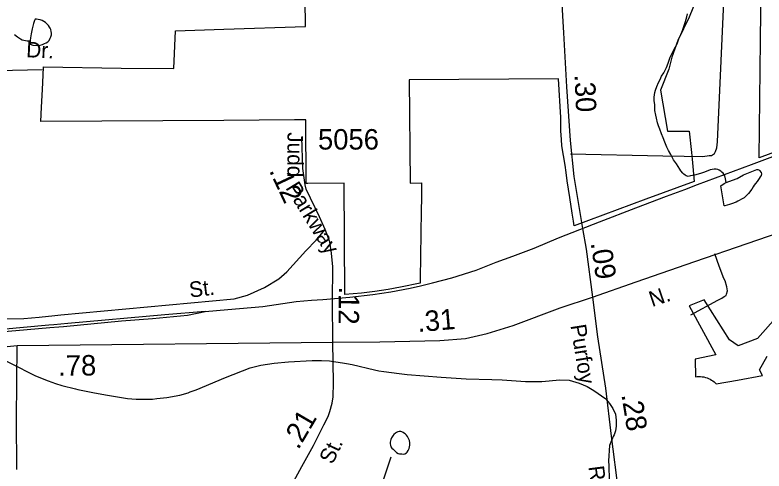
# Model space of a CAD drawing. Extents: x 2001466 to 2224147, y 644118 to 847247.
# Drawn here: x 2063724 to 2068297, y 669606 to 672391 of the extents above; entities that cross this region are included whole.
import ezdxf

# ---------------------------------------------------------------- set-up
doc = ezdxf.new("R2010")
doc.units = 0
for name, color, linetype in [('Exist Boundary Political City Limit New', 7, 'Continuous'), ('Exist Hydrographic Creek Single Shore', 7, 'Continuous'), ('Exist Hydrographic Misc Water Feature', 7, 'Continuous'), ('Exist Railroad Mainline', 7, 'Continuous'), ('Exist Railroad Siding', 7, 'Continuous'), ('Exist Road Non-System Type 51', 7, 'Continuous'), ('Exist Road Non-System Type 51 Label', 7, 'Continuous'), ('Exist Road Primary US Attributed', 7, 'Continuous'), ('Exist Road Primary US Label', 7, 'Continuous'), ('Exist Road Primary US Mileage Hundredths English Label', 7, 'Continuous'), ('Exist Road Secondary Mileage Hundredths English Label', 7, 'Continuous'), ('Exist Road Secondary Type 51 Attributed', 7, 'Continuous'), ('Exist Road Secondary Type 51 Label', 7, 'Continuous'), ('Exist Road Secondary Type 51 Number Label', 7, 'Continuous'), ('Map Preparation Boundary City Limit Buffer Line', 7, 'Continuous')]:
    doc.layers.add(name, color=color, linetype=linetype)

msp = doc.modelspace()

# ---------------------------------------------------------------- linework, layer by layer
at = {"layer": 'Exist Boundary Political City Limit New'}
for points in [[(2065738, 670683.3), (2065734, 671363.3), (2065512.2, 671362.5), (2065501.5, 671362.4), (2065500.1, 671750.2), (2065430, 671749.7), (2065000, 671747.1), (2063882.2, 671740.3), (2063886.4, 671827.8), (2063891.6, 671936.2), (2063895.8, 672023.8), (2063897.6, 672073.8), (2064372.4, 672067), (2064693.1, 672064.7), (2064703.1, 672294), (2065000, 672303.5), (2065496.6, 672319.8), (2065489.2, 672981.5)], [(2068496.8, 671603.3), (2068267.1, 671519.3), (2068275.2, 672234.5), (2068284, 672935.8)], [(2067883.5, 672490.1), (2067839, 672378.1), (2067770.8, 672235.2), (2067733.8, 672132.6), (2067716.2, 672059.8), (2067665.4, 671931.4), (2067706.6, 671682.1), (2067840.1, 671681), (2067853.2, 671552.2), (2067857.1, 671510.6), (2067870.1, 671373.8), (2067575.9, 671265.8), (2067136.6, 671103.7), (2067132.6, 671132.4), (2067125.5, 671180.9), (2067110.6, 671275.8), (2067095.5, 671378.6), (2067088.5, 671429.1), (2067082.8, 671473.8), (2067062.6, 671592.8), (2067059.8, 671629.7), (2067055.6, 671684.5), (2067056.4, 671764.5), (2067042.6, 672000.1), (2066130.4, 671994.4), (2066136.9, 671364.8), (2066206, 671365), (2066204.8, 671266.1), (2066204, 671202.1), (2066203.9, 671195.1), (2066198.4, 670779.1), (2066198.1, 670753.1), (2066077.8, 670728.9), (2066001.5, 670715.1), (2065920.4, 670702.7), (2065839, 670692.6), (2065738, 670683.3)], [(2068384.8, 670560.4), (2068257.6, 670415.1), (2068139.5, 670369.8), (2068085, 670406.1), (2067930.6, 670651.1), (2067839.9, 670614.8), (2068003.2, 670315.2), (2067876.1, 670288), (2067878.9, 670181.9), (2067889, 670182.9), (2067899, 670183.3), (2067909.1, 670183), (2067919.2, 670182), (2067929.1, 670180.2), (2067939, 670177.8), (2067948.6, 670174.8), (2067958, 670171), (2067967.1, 670166.6), (2067975.9, 670161.6), (2067984.2, 670155.9), (2067992.2, 670149.8), (2067999.8, 670143.1), (2068005.4, 670137.8), (2068135, 670161), (2068286.9, 670189.7), (2068268.8, 670224.1), (2068316.5, 670307.3)]]:
    msp.add_lwpolyline(points, dxfattribs=at)
at = {"layer": 'Exist Hydrographic Creek Single Shore'}
msp.add_lwpolyline([(2066179.8, 668236.4), (2066132.3, 668352.2), (2066106.2, 668608.7), (2066031.2, 668843.1), (2065972.3, 668942.7), (2065930.3, 669117.5), (2065938.3, 669448.7), (2066021.3, 669693)], dxfattribs=at)
at = {"layer": 'Exist Hydrographic Misc Water Feature'}
for p, q in [((2063824.8, 670200.3), (2063850.4, 670187.5)), ((2064093.4, 670107.1), (2064108.4, 670103.3)), ((2067258.2, 670096.8), (2067330.4, 670045.7)), ((2067258.2, 670096.8), (2067330.4, 670045.7)), ((2067330.4, 670045.7), (2067343.7, 670030)), ((2067330.4, 670045.7), (2067343.7, 670030)), ((2067393.7, 669916.4), (2067394.4, 669911.5))]:
    msp.add_line(p, q, dxfattribs=at)
for points in [[(2068065.9, 671367.2), (2068061.8, 671391), (2068057.5, 671409), (2068047.5, 671425.2), (2068039.5, 671431.2), (2068033.7, 671437), (2068023.7, 671442.9), (2068013.6, 671446.9), (2068003.8, 671448.8), (2067991.5, 671449), (2067967.9, 671444.9), (2067943.7, 671434.8), (2067927.7, 671428.7), (2067915.6, 671424.8), (2067895.5, 671419), (2067871.5, 671412.9), (2067859.8, 671410.6), (2067847.9, 671408.8), (2067833.8, 671404.9), (2067821.5, 671408.7), (2067816, 671412.8), (2067808, 671418.5), (2067801.8, 671424.7), (2067789.5, 671438.7), (2067781.7, 671450.4), (2067771.7, 671466.5), (2067761.6, 671482.7), (2067743.6, 671506.5), (2067727.6, 671538.6), (2067713.4, 671562.6), (2067703.4, 671584.4), (2067691.3, 671614.2), (2067681.2, 671640.5), (2067671.2, 671664.3), (2067661.3, 671694.2), (2067653.1, 671714.5), (2067647.2, 671732.4), (2067639.2, 671760.4), (2067635.3, 671780), (2067629.4, 671808.1), (2067629.1, 671842.3), (2067626.9, 671868.1), (2067626.9, 671890.1), (2067630.6, 671918.3), (2067634.7, 671932.3), (2067643.1, 671954.1), (2067652.5, 671978.2), (2067662.8, 671996.1), (2067670.8, 672016.4), (2067684.7, 672038.3), (2067700.7, 672070.3), (2067710.6, 672096.4), (2067724.5, 672134.4), (2067734.5, 672154.4), (2067748.3, 672182.4), (2067766.3, 672214.5), (2067776, 672244.6), (2067788.3, 672272.4), (2067798.3, 672296.4), (2067808.4, 672326.5), (2067816.2, 672350.5), (2067826, 672380.6), (2067829.7, 672398.3)], [(2063817.4, 672231), (2063817.4, 672222.9), (2063817.4, 672213.2), (2063833.4, 672207.1), (2063863.2, 672205), (2063877.3, 672207.3), (2063893.1, 672211), (2063905.2, 672217.3), (2063915.2, 672221.1), (2063925.1, 672227.3), (2063932.9, 672235.4), (2063939, 672249.5), (2063942.9, 672257.4), (2063947, 672269.4), (2063947, 672279.1), (2063944.8, 672291.2), (2063942.9, 672303.2), (2063939.2, 672311.1), (2063935.1, 672317.4), (2063929.2, 672327.2), (2063921.2, 672335.3), (2063910.9, 672345.4), (2063900.9, 672351.4), (2063890.6, 672357), (2063876.9, 672361.1), (2063866.6, 672363.1), (2063855.2, 672365.2), (2063847, 672365.2), (2063842.7, 672357), (2063840.8, 672351.2), (2063836.7, 672339.2), (2063833.2, 672323.1), (2063828.9, 672307.1), (2063825, 672287), (2063823.2, 672275.2), (2063821.1, 672262.9), (2063819.1, 672251.1), (2063817.2, 672235.1), (2063817.4, 672231)], [(2063817.4, 672231), (2063799.2, 672231), (2063778.9, 672234.8), (2063769, 672237.1), (2063757.4, 672243), (2063738.9, 672255.1), (2063721.3, 672270.7)], [(2068065.9, 671367.2), (2068081.7, 671373.3), (2068131.9, 671393.3), (2068171.7, 671415.3), (2068211.3, 671431.6), (2068241.8, 671443.6), (2068253.5, 671447.5), (2068259.5, 671447.4), (2068265.6, 671445.7), (2068269.5, 671441.4), (2068279.4, 671429.4), (2068281.6, 671421.7), (2068279.8, 671411.4), (2068273.8, 671403.4), (2068267.5, 671393.4), (2068261.9, 671385.4), (2068253.9, 671373.6), (2068243.9, 671361.3), (2068235.9, 671351.6), (2068230, 671341.5), (2068221.5, 671327.4), (2068202.1, 671301.6), (2068184.2, 671281.5), (2068176, 671273.5), (2068159.8, 671265.4), (2068145.7, 671257.4), (2068136, 671253.1), (2068125.8, 671247.4), (2068097.7, 671237.1), (2068086, 671233.1), (2068072.3, 671229.2), (2068057.9, 671225.2), (2068054, 671225), (2068045.8, 671275.3), (2068039.9, 671311.1), (2068031.9, 671347.2), (2068053.8, 671360.9), (2068065.9, 671367.2)], [(2063443.2, 670371.3), (2063512.3, 670348), (2063571.4, 670325.3), (2063615.3, 670305.2), (2063824.8, 670200.3)], [(2063443.2, 670371.3), (2063512.3, 670348), (2063571.4, 670325.3), (2063615.3, 670305.2), (2063824.8, 670200.3)], [(2064793.9, 670088.6), (2064830.4, 670102), (2065009.4, 670176.2), (2065160.3, 670235.3), (2065224.3, 670252.3), (2065305.3, 670264.8), (2065394.3, 670273.5), (2065538.2, 670281.8), (2065595.2, 670281.7), (2065643.2, 670278.2)], [(2064793.9, 670088.6), (2064830.4, 670102), (2065009.4, 670176.2), (2065160.3, 670235.3), (2065224.3, 670252.3), (2065305.3, 670264.8), (2065394.3, 670273.5), (2065538.2, 670281.8), (2065595.2, 670281.7), (2065643.2, 670278.2)], [(2065643.2, 670278.2), (2065655.3, 670277.3), (2065723.4, 670267.4), (2065748.2, 670262.4)], [(2065643.2, 670278.2), (2065655.3, 670277.3), (2065723.4, 670267.4), (2065748.2, 670262.4)], [(2065748.2, 670262.4), (2065782.2, 670255.8), (2065919.2, 670223.3), (2065946.1, 670218.3)], [(2065748.2, 670262.4), (2065782.2, 670255.8), (2065919.2, 670223.3), (2065946.1, 670218.3)], [(2063850.4, 670187.5), (2063926.3, 670155.7), (2063972, 670140.8)], [(2063850.4, 670187.5), (2063926.3, 670155.7), (2063972, 670140.8)], [(2065946.1, 670218.3), (2065975.6, 670212.9), (2066069.9, 670201.6)], [(2065946.1, 670218.3), (2065975.6, 670212.9), (2066069.9, 670201.6)], [(2066069.9, 670201.6), (2066117.3, 670195.9), (2066325.2, 670178.2)], [(2066069.9, 670201.6), (2066117.3, 670195.9), (2066325.2, 670178.2)], [(2066325.2, 670178.2), (2066479.2, 670169.3), (2066634, 670164.7)], [(2066325.2, 670178.2), (2066479.2, 670169.3), (2066634, 670164.7)], [(2063972, 670140.8), (2064009.4, 670128.5), (2064093.4, 670107.1)], [(2063972, 670140.8), (2064009.4, 670128.5), (2064093.4, 670107.1)], [(2066634, 670164.7), (2066697.4, 670162.8), (2066840.3, 670153.3), (2066889.3, 670152), (2066939.6, 670153.2), (2067050.3, 670162.8)], [(2066634, 670164.7), (2066697.4, 670162.8), (2066840.3, 670153.3), (2066889.3, 670152), (2066939.6, 670153.2), (2067050.3, 670162.8)], [(2067050.3, 670162.8), (2067106.3, 670160), (2067167.4, 670143.4)], [(2067050.3, 670162.8), (2067106.3, 670160), (2067167.4, 670143.4)], [(2067167.4, 670143.4), (2067216.4, 670121.1), (2067258.2, 670096.8)], [(2067167.4, 670143.4), (2067216.4, 670121.1), (2067258.2, 670096.8)], [(2064108.4, 670103.3), (2064198.4, 670084.8), (2064277.2, 670070.5), (2064410, 670049.5), (2064463.8, 670045.4)], [(2064108.4, 670103.3), (2064198.4, 670084.8), (2064277.2, 670070.5), (2064410, 670049.5), (2064463.8, 670045.4)], [(2064730.5, 670069.5), (2064781.4, 670084.1), (2064793.9, 670088.6)], [(2064730.5, 670069.5), (2064781.4, 670084.1), (2064793.9, 670088.6)], [(2064463.8, 670045.4), (2064481.4, 670044), (2064564.2, 670045.6), (2064589.5, 670048.2)], [(2064463.8, 670045.4), (2064481.4, 670044), (2064564.2, 670045.6), (2064589.5, 670048.2)], [(2064589.5, 670048.2), (2064650.4, 670054.3), (2064730.5, 670069.5)], [(2064589.5, 670048.2), (2064650.4, 670054.3), (2064730.5, 670069.5)], [(2067343.7, 670030), (2067354.2, 670017.8), (2067374.3, 669987.6)], [(2067343.7, 670030), (2067354.2, 670017.8), (2067374.3, 669987.6)], [(2067374.3, 669987.6), (2067389.2, 669953.1), (2067393.7, 669916.4)], [(2067374.3, 669987.6), (2067389.2, 669953.1), (2067393.7, 669916.4)], [(2067394.4, 669911.5), (2067393.3, 669880.2), (2067389.2, 669850.6), (2067382.5, 669826.9), (2067375.7, 669816.2)], [(2067394.4, 669911.5), (2067393.3, 669880.2), (2067389.2, 669850.6), (2067382.5, 669826.9), (2067375.7, 669816.2)], [(2066033.2, 669739.7), (2066053.1, 669719.7), (2066063.2, 669713.8), (2066071.2, 669711.8), (2066085.1, 669709.8), (2066093.1, 669707.8), (2066103.2, 669711.8), (2066113.2, 669717.8), (2066119.1, 669721.8), (2066125.1, 669731.9), (2066131.2, 669743.9), (2066133.1, 669753.9), (2066135.1, 669763.9), (2066135.1, 669777.9), (2066133.1, 669791.9), (2066125.1, 669807.9), (2066121, 669815.9), (2066115, 669823.9), (2066108.9, 669829.9), (2066102.9, 669835.8), (2066092.9, 669841.8), (2066084.9, 669845.8), (2066079, 669847.8), (2066068.9, 669847.8), (2066060.9, 669845.7), (2066052.9, 669841.7), (2066047, 669837.7), (2066037.1, 669829.7), (2066031, 669821.6), (2066027.1, 669813.7), (2066023, 669807.7), (2066019.1, 669797.7), (2066017, 669789.7), (2066015, 669781.7), (2066015, 669771.7), (2066017.2, 669763.7), (2066019.1, 669753.7), (2066025.2, 669745.7), (2066033.2, 669739.7)], [(2067375.7, 669816.2), (2067353.4, 669760.8), (2067347.2, 669667.1), (2067348.2, 669638.2)], [(2067375.7, 669816.2), (2067353.4, 669760.8), (2067347.2, 669667.1), (2067348.2, 669638.2)], [(2067348.2, 669638.2), (2067351.3, 669552.9), (2067360.3, 669439.8)], [(2067348.2, 669638.2), (2067351.3, 669552.9), (2067360.3, 669439.8)]]:
    msp.add_lwpolyline(points, dxfattribs=at)
at = {"layer": 'Exist Railroad Mainline'}
for points in [[(2067171.7, 671081), (2067291.9, 671127.3), (2067513.8, 671213.4), (2067701.8, 671283.5), (2067812.6, 671326.1), (2067889.7, 671355.7), (2068220.9, 671477.9), (2068253.6, 671489.9), (2068637.6, 671634.1), (2069017.5, 671776.4), (2069389.4, 671910.9), (2069773.3, 672053.1), (2070137.2, 672185.3), (2070333.9, 672257.2)], [(2064886.1, 670579.1), (2065024.4, 670592.8), (2065236.4, 670610.7), (2065440.2, 670641.9), (2065534.9, 670648.4), (2065603, 670653.9), (2065769.1, 670668.1), (2065908.3, 670684.5), (2066018.4, 670700.7), (2066135.7, 670721.6), (2066200.4, 670736.2), (2066273.6, 670755.7), (2066391.1, 670785.6), (2066538.6, 670832), (2066660.6, 670880.7), (2066763.1, 670917.3), (2066892.5, 670966.1), (2067041.9, 671030.9), (2067171.7, 671081)], [(2061615.3, 670546.4), (2061794.5, 670479.1), (2061925.3, 670432), (2062043.1, 670401), (2062164.4, 670375.6), (2062260.2, 670360.4), (2062367.4, 670352.5), (2062477.3, 670350.2), (2062619, 670358.9), (2062757, 670369.6), (2062933.2, 670385.8), (2063244.5, 670414), (2063542.8, 670447.3), (2063935.9, 670482.5)], [(2063935.9, 670482.5), (2063992.1, 670487.1), (2064019.8, 670489.3), (2064375.1, 670522.3), (2064564.3, 670536.5), (2064777.1, 670557), (2064886.1, 670579.1)]]:
    msp.add_lwpolyline(points, dxfattribs=at)
at = {"layer": 'Exist Railroad Siding'}
for points in [[(2063930.4, 670495.7), (2063643.2, 670470.4), (2063452.6, 670445.2), (2062937.2, 670419.6), (2062850.9, 670412.8), (2062568.7, 670389.7), (2062401.2, 670389.1), (2062241.6, 670404.4), (2062146.3, 670419.1), (2062022.8, 670447.3), (2061889.2, 670481.7), (2061708.9, 670535.5), (2061615.3, 670546.4)], [(2064886.1, 670579.1), (2064638.3, 670560.4), (2064046.2, 670506.3), (2063960.6, 670498.2), (2063930.4, 670495.7)]]:
    msp.add_lwpolyline(points, dxfattribs=at)
at = {"layer": 'Exist Road Non-System Type 51'}
for p, q in [((2063524, 672049.3), (2063890.6, 672058.6)), ((2067115.7, 671543.8), (2067678, 671530.8)), ((2068023.3, 670857.6), (2067995.3, 670932))]:
    msp.add_line(p, q, dxfattribs=at)
for points in [[(2067678, 671530.8), (2067809.4, 671527.8), (2067923.4, 671527.4), (2067961.5, 671532.7), (2067975.5, 671532.4), (2067993.8, 671546), (2068000, 671557.9), (2068008.5, 671579.7), (2068013.2, 671615.6), (2068057.4, 672608.7), (2067994.8, 672697.6), (2067991.2, 672698.1), (2067939.2, 672697.1), (2067845.6, 672699.7)], [(2067849.1, 670559.1), (2068015.5, 670649.6), (2068039.8, 670661.1), (2068054, 670670.8), (2068066.1, 670678.5), (2068068.3, 670686.5), (2068072.7, 670706.4), (2068069.2, 670730.5), (2068059.9, 670766.7), (2068052.2, 670780.8), (2068023.3, 670857.6)], [(2063736.1, 670371.8), (2063731.9, 669924.3), (2063732.5, 669614.2)]]:
    msp.add_lwpolyline(points, dxfattribs=at)
at = {"layer": 'Exist Road Primary US Attributed'}
for points in [[(2067248.5, 670668.2), (2067515.3, 670761.4), (2067873.8, 670885), (2068512.2, 671104.9), (2069417.4, 671419.1), (2069697.9, 671513.4), (2069984.6, 671607.6), (2070426.2, 671762.6)], [(2065664.7, 670392.6), (2065950.3, 670394.3), (2066318.1, 670402.8), (2066474.1, 670415.8), (2066605.9, 670445.2), (2066765, 670495.4), (2067051.7, 670602.3), (2067248.5, 670668.2)], [(2061546.2, 670250.4), (2061679.9, 670254.6), (2061992.8, 670260.9), (2062298.4, 670265), (2062649.5, 670278.7), (2063102.2, 670317.4), (2063470.5, 670346.7), (2063738.4, 670371.9), (2065664.7, 670392.6)]]:
    msp.add_lwpolyline(points, dxfattribs=at)
at = {"layer": 'Exist Road Secondary Type 51 Attributed'}
for points in [[(2067047.9, 672703.9), (2067073.2, 672281.5), (2067090.5, 671953.1), (2067112.6, 671623.8), (2067136.3, 671404.3), (2067189.3, 671087.7)], [(2065617, 671080), (2065583.9, 671158.4), (2065501.1, 671327.9), (2065495.4, 671352.8), (2065480.7, 671452.5), (2065475, 671645.3)], [(2061545, 670645.5), (2061608, 670629.6), (2061734.2, 670612.3), (2063279.4, 670542.3), (2063591.9, 670534.7), (2063778.8, 670538.2), (2063872.5, 670545.9), (2063967.9, 670555.3), (2064004.5, 670559.5), (2065061.2, 670658.2), (2065142.6, 670680.5), (2065247.6, 670726.5), (2065334.3, 670779), (2065384.6, 670821.9), (2065500.4, 670949.7), (2065562, 671015.6), (2065617, 671080)], [(2065664.7, 670392.6), (2065662.6, 670641.3), (2065665.1, 670852.6), (2065656.2, 670936.9), (2065646.8, 671005.1), (2065617, 671080)], [(2067189.3, 671087.7), (2067210.4, 670961.4), (2067248.5, 670668.2)], [(2067248.5, 670668.2), (2067280.8, 670424.7), (2067328.3, 670111), (2067363.7, 669818.4), (2067405.9, 669484.7), (2067446.5, 669206.9)], [(2065320.2, 669350.5), (2065475.1, 669633), (2065546.4, 669760.7), (2065610.2, 669888.3), (2065635.7, 669939.4), (2065646, 669969.2), (2065659.6, 670019.5), (2065665.5, 670058.7), (2065668.1, 670143.8), (2065664.7, 670392.6)]]:
    msp.add_lwpolyline(points, dxfattribs=at)
at = {"layer": 'Map Preparation Boundary City Limit Buffer Line'}
for points in [[(2065738, 670683.3), (2065734, 671363.3), (2065512.2, 671362.5), (2065501.5, 671362.4), (2065500.1, 671750.2), (2065430, 671749.7), (2065000, 671747.1), (2063882.2, 671740.3), (2063886.4, 671827.8), (2063891.6, 671936.2), (2063895.8, 672023.8), (2063897.6, 672073.8), (2064372.4, 672067), (2064693.1, 672064.7), (2064703.1, 672294), (2065000, 672303.5), (2065496.6, 672319.8), (2065489.2, 672981.5)], [(2068496.8, 671603.3), (2068267.1, 671519.3), (2068275.2, 672234.5), (2068284, 672935.8)], [(2067883.5, 672490.1), (2067839, 672378.1), (2067770.8, 672235.2), (2067733.8, 672132.6), (2067716.2, 672059.8), (2067665.4, 671931.4), (2067706.6, 671682.1), (2067840.1, 671681), (2067853.2, 671552.2), (2067857.1, 671510.6), (2067870.1, 671373.8), (2067575.9, 671265.8), (2067136.6, 671103.7), (2067132.6, 671132.4), (2067125.5, 671180.9), (2067110.6, 671275.8), (2067095.5, 671378.6), (2067088.5, 671429.1), (2067082.8, 671473.8), (2067062.6, 671592.8), (2067059.8, 671629.7), (2067055.6, 671684.5), (2067056.4, 671764.5), (2067042.6, 672000.1), (2066130.4, 671994.4), (2066136.9, 671364.8), (2066206, 671365), (2066204.8, 671266.1), (2066204, 671202.1), (2066203.9, 671195.1), (2066198.4, 670779.1), (2066198.1, 670753.1), (2066077.8, 670728.9), (2066001.5, 670715.1), (2065920.4, 670702.7), (2065839, 670692.6), (2065738, 670683.3)], [(2068384.8, 670560.4), (2068257.6, 670415.1), (2068139.5, 670369.8), (2068085, 670406.1), (2067930.6, 670651.1), (2067839.9, 670614.8), (2068003.2, 670315.2), (2067876.1, 670288), (2067878.9, 670181.9), (2067889, 670182.9), (2067899, 670183.3), (2067909.1, 670183), (2067919.2, 670182), (2067929.1, 670180.2), (2067939, 670177.8), (2067948.6, 670174.8), (2067958, 670171), (2067967.1, 670166.6), (2067975.9, 670161.6), (2067984.2, 670155.9), (2067992.2, 670149.8), (2067999.8, 670143.1), (2068005.4, 670137.8), (2068135, 670161), (2068286.9, 670189.7), (2068268.8, 670224.1), (2068316.5, 670307.3)]]:
    msp.add_lwpolyline(points, dxfattribs=at)

# ---------------------------------------------------------------- texts
at = {"layer": 'Exist Road Non-System Type 51 Label'}
msp.add_text('Dr.', height=95, rotation=357.4041, dxfattribs=at).set_placement((2063791, 672133.2))
at = {"layer": 'Exist Road Primary US Label'}
msp.add_text('N. ', height=95, rotation=18.8441, dxfattribs=at).set_placement((2067613.6, 670606.8))
at = {"layer": 'Exist Road Primary US Mileage Hundredths English Label'}
for s, rotation, p in [('.31', 4.7806, (2066184.5, 670454.3)), ('.78', 0.6163, (2063988.4, 670187))]:
    msp.add_text(s, height=125, rotation=rotation, dxfattribs=at).set_placement(p)
at = {"layer": 'Exist Road Secondary Mileage Hundredths English Label'}
for s, rotation, p in [('.30', 272.4859, (2067139.4, 672026.7)), ('.12', 295.1561, (2065273.5, 671441)), ('.09', 278.5528, (2067238, 670998.8)), ('.12', 269.395, (2065701.4, 670733)), ('.28', 279.1387, (2067425.4, 670071.6)), ('.21', 59.673, (2065453.5, 669731.7))]:
    msp.add_text(s, height=125, rotation=rotation, dxfattribs=at).set_placement(p)
at = {"layer": 'Exist Road Secondary Type 51 Label'}
for s, rotation, p in [('Judd', 270, (2065387.5, 671675)), ('Parkway', 301.525, (2065373, 671335.5)), (' St.', 6.8409, (2064757.8, 670660.7)), ('Purfoy', 279.1387, (2067114.9, 670494.8)), (' St.', 64.1575, (2065646.7, 669609.6)), ('Rd.', 277.3749, (2067224.4, 669632.7))]:
    msp.add_text(s, height=95, rotation=rotation, dxfattribs=at).set_placement(p)
at = {"layer": 'Exist Road Secondary Type 51 Number Label'}
msp.add_text('5056', height=125, dxfattribs=at).set_placement((2065573.9, 671569.1))

doc.saveas('drawing.dxf')
